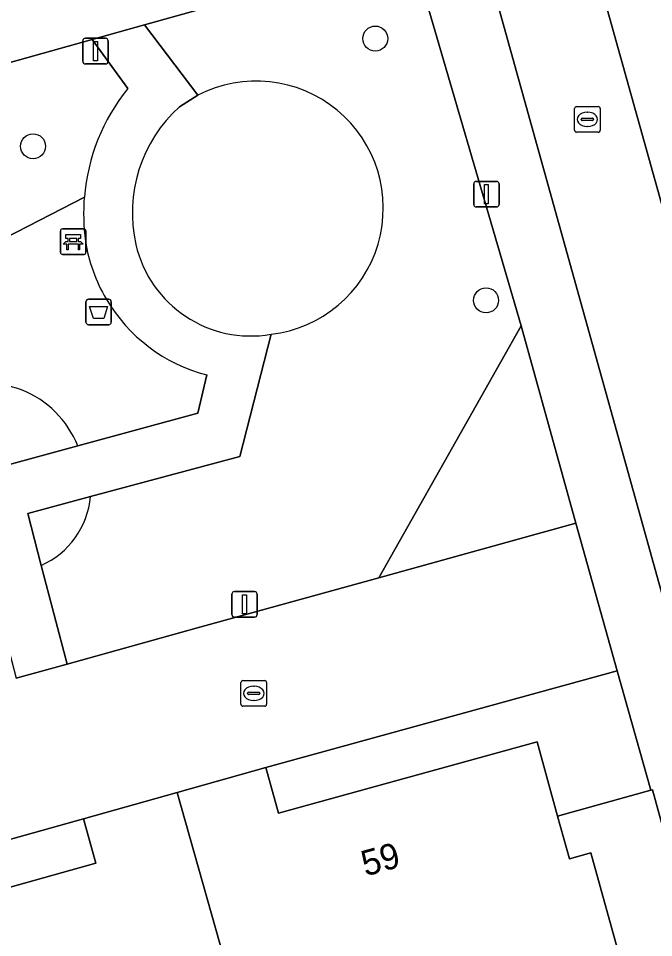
# Model space of a CAD drawing. Extents: x 159626 to 160723, y 388173 to 389416.
# Drawn here: x 159837.12 to 159861.97, y 388412.83 to 388448.77 of the extents above; entities that cross this region are included whole.
import ezdxf

# ---------------------------------------------------------------- set-up
doc = ezdxf.new("R2010")
doc.units = 0
for name, color, linetype in [('IMGEO_Afvalbak', 7, 'Continuous'), ('IMGEO_Bank', 7, 'Continuous'), ('IMGEO_Boom', 7, 'Continuous'), ('IMGEO_Erf', 7, 'Continuous'), ('IMGEO_Groenvoorziening', 7, 'Continuous'), ('IMGEO_Kolk', 7, 'Continuous'), ('IMGEO_Lichtmast', 7, 'Continuous'), ('IMGEO_Pand', 7, 'Continuous'), ('IMGEO_Pand_nummerreeks', 7, 'Continuous'), ('IMGEO_Rijbaan_lokaal_open', 7, 'Continuous'), ('IMGEO_Terreindeel_open', 7, 'Continuous'), ('IMGEO_Voetpad_open', 7, 'Continuous')]:
    doc.layers.add(name, color=color, linetype=linetype)

msp = doc.modelspace()

# ---------------------------------------------------------------- linework, layer by layer
at = {"layer": 'IMGEO_Afvalbak'}
for p, q in [((159839.768, 388436.896), (159839.768, 388437.696)), ((159839.768, 388437.696), (159839.768, 388436.896)), ((159839.868, 388437.796), (159840.658, 388437.796)), ((159840.658, 388437.796), (159839.868, 388437.796)), ((159840.758, 388437.696), (159840.758, 388436.896)), ((159840.758, 388436.896), (159840.758, 388437.696)), ((159840.658, 388436.796), (159839.868, 388436.796)), ((159839.868, 388436.796), (159840.658, 388436.796))]:
    msp.add_line(p, q, dxfattribs=at)
msp.add_lwpolyline([(159839.911, 388437.51), (159840.615, 388437.51), (159840.466, 388437.04), (159840.06, 388437.04), (159839.911, 388437.51)], dxfattribs=at)
for centre, start, end in [((159839.868, 388437.696), 90, 180), ((159839.868, 388437.696), 90, 180), ((159840.658, 388437.696), 0, 90), ((159840.658, 388437.696), 360, 90), ((159839.868, 388436.896), 180, 270), ((159839.868, 388436.896), 180, 270), ((159840.658, 388436.896), 270, 0), ((159840.658, 388436.896), 270, 0)]:
    msp.add_arc(centre, 0.1, start, end, dxfattribs=at)
at = {"layer": 'IMGEO_Bank'}
for p, q in [((159838.768, 388439.619), (159838.768, 388440.46)), ((159838.768, 388440.46), (159838.768, 388439.619)), ((159838.843, 388440.544), (159839.684, 388440.544)), ((159839.684, 388440.544), (159838.843, 388440.544)), ((159839.768, 388440.469), (159839.768, 388439.628)), ((159839.768, 388439.628), (159839.768, 388440.469)), ((159839.465, 388439.942), (159839.072, 388439.942)), ((159839.077, 388440.05), (159839.077, 388440.156)), ((159839.121, 388440.156), (159839.121, 388440.05)), ((159839.409, 388440.162), (159839.127, 388440.162)), ((159839.127, 388440.044), (159839.409, 388440.044)), ((159839.415, 388440.05), (159839.415, 388440.156)), ((159839.459, 388440.156), (159839.459, 388440.05)), ((159839.693, 388439.544), (159838.852, 388439.544)), ((159838.852, 388439.544), (159839.693, 388439.544))]:
    msp.add_line(p, q, dxfattribs=at)
for points in [[(159839.071, 388440.162), (159838.985, 388440.162), (159838.985, 388440.323), (159839.548, 388440.323), (159839.548, 388440.162), (159839.465, 388440.162)], [(159839.015, 388439.942), (159838.873, 388439.942), (159838.985, 388440.044), (159839.071, 388440.044)], [(159839.065, 388439.935), (159839.065, 388439.728), (159839.022, 388439.728), (159839.022, 388439.935)], [(159839.465, 388440.044), (159839.548, 388440.044), (159839.66, 388439.942), (159839.521, 388439.942)], [(159839.515, 388439.935), (159839.515, 388439.728), (159839.471, 388439.728), (159839.471, 388439.935)]]:
    msp.add_lwpolyline(points, dxfattribs=at)
for centre, radius, start, end in [((159838.846, 388440.466), 0.0779, 92.4484, 184.2845), ((159838.846, 388440.466), 0.0779, 92.4484, 184.2845), ((159839.69, 388440.466), 0.0779, 2.4484, 94.2845), ((159839.69, 388440.466), 0.0779, 2.4484, 94.2845), ((159839.015, 388439.935), 0.00671, 2.8957, 87.1043), ((159839.072, 388439.935), 0.00671, 92.8957, 177.1043), ((159839.07, 388440.155), 0.00671, 2.8957, 87.1043), ((159839.07, 388440.051), 0.00671, 272.8957, 357.1043), ((159839.127, 388440.155), 0.00671, 92.8957, 177.1043), ((159839.127, 388440.051), 0.00671, 182.8957, 267.1043), ((159839.409, 388440.155), 0.00671, 2.8957, 87.1043), ((159839.409, 388440.051), 0.00671, 272.8957, 357.1043), ((159839.466, 388440.155), 0.00671, 92.8957, 177.1043), ((159839.466, 388440.051), 0.00671, 182.8957, 267.1043), ((159839.464, 388439.935), 0.00671, 2.8957, 87.1043), ((159839.521, 388439.935), 0.00671, 92.8957, 177.1043), ((159838.846, 388439.622), 0.0779, 182.4484, 274.2845), ((159838.846, 388439.622), 0.0779, 182.4484, 274.2845), ((159839.69, 388439.622), 0.0779, 272.4484, 4.2845), ((159839.69, 388439.622), 0.0779, 272.4484, 4.2845)]:
    msp.add_arc(centre, radius, start, end, dxfattribs=at)
at = {"layer": 'IMGEO_Boom'}
for centre in [(159851.082, 388447.985), (159837.698, 388443.774), (159855.414, 388437.748)]:
    msp.add_circle(centre, 0.489, dxfattribs=at)
at = {"layer": 'IMGEO_Erf'}
msp.add_lwpolyline([(159860.545, 388423.261), (159846.806, 388419.48), (159847.3, 388417.69), (159857.414, 388420.486), (159858.215, 388417.585), (159861.857, 388418.591)], close=True, dxfattribs=at)
msp.add_lwpolyline([(159830.091, 388412.921), (159840.153, 388415.744), (159839.667, 388417.477), (159825.91, 388413.624)], dxfattribs=at)
at = {"layer": 'IMGEO_Groenvoorziening'}
for points in [[(159856.782, 388436.748), (159852.499, 388451.444), (159842.058, 388448.523), (159844.146, 388445.771)], [(159841.398, 388446.031), (159840.008, 388447.95), (159826.869, 388444.275), (159824.589, 388440.247), (159824.515, 388440.117), (159827.303, 388430.087), (159831.259, 388432.395), (159829.968, 388436.783), (159839.703, 388441.786)], [(159844.146, 388445.771), (159843.43, 388445.32)], [(159839.703, 388441.786), (159829.968, 388436.783), (159831.259, 388432.395), (159833.723, 388433.861)], [(159838.018, 388427.383), (159839.027, 388423.524), (159844.081, 388424.925), (159851.216, 388426.903), (159856.782, 388436.748)], [(159847.006, 388436.421), (159845.791, 388431.645), (159839.947, 388430.073)], [(159839.443, 388432.058), (159844.144, 388433.339), (159844.5, 388434.83)]]:
    msp.add_lwpolyline(points, dxfattribs=at)
msp.add_lwpolyline([(159856.782, 388436.748), (159851.216, 388426.903), (159858.925, 388429.04)], close=True, dxfattribs=at)
for centre, radius, start, end in [((159846.424, 388441.355), 4.969, 276.7287, 117.2872), ((159846.424, 388441.355), 4.969, 276.7287, 117.2872), ((159847.529, 388441.122), 7.854, 141.3168, 175.1502), ((159847.157, 388441.17), 5.578, 131.9241, 192.8713), ((159847.559, 388441.127), 7.884, 175.2053, 187.7272), ((159846.091, 388441.062), 6.422, 188.9115, 210.4635), ((159846.22, 388440.976), 4.622, 193.1132, 279.7872), ((159846.111, 388441.066), 6.441, 210.4092, 255.517), ((159835.854, 388430.645), 3.858, 21.4873, 116.3073), ((159836.669, 388430.387), 3.293, 294.1862, 354.5251)]:
    msp.add_arc(centre, radius, start, end, dxfattribs=at)
at = {"layer": 'IMGEO_Kolk'}
for p, q in [((159858.877, 388444.398), (159858.877, 388445.25)), ((159858.952, 388445.324), (159859.804, 388445.324)), ((159859.878, 388445.25), (159859.878, 388444.398)), ((159859.365, 388445.104), (159859.39, 388445.104)), ((159859.136, 388444.818), (159859.136, 388444.83)), ((159859.574, 388444.781), (159859.176, 388444.781)), ((159859.179, 388444.867), (159859.577, 388444.867)), ((159859.388, 388444.544), (159859.363, 388444.544)), ((159859.62, 388444.83), (159859.62, 388444.818)), ((159859.804, 388444.324), (159858.952, 388444.324)), ((159845.829, 388421.953), (159845.829, 388422.805)), ((159845.904, 388422.879), (159846.756, 388422.879)), ((159846.317, 388422.659), (159846.342, 388422.659)), ((159846.83, 388422.805), (159846.83, 388421.953)), ((159846.088, 388422.373), (159846.088, 388422.385)), ((159846.526, 388422.336), (159846.128, 388422.336)), ((159846.131, 388422.422), (159846.529, 388422.422)), ((159846.572, 388422.385), (159846.572, 388422.373)), ((159846.756, 388421.879), (159845.904, 388421.879)), ((159846.34, 388422.099), (159846.315, 388422.099))]:
    msp.add_line(p, q, dxfattribs=at)
for points in [[(159858.877, 388444.398), (159858.877, 388445.25)], [(159858.952, 388445.324), (159859.804, 388445.324)], [(159859.878, 388445.25), (159859.878, 388444.398)], [(159859.804, 388444.324), (159858.952, 388444.324)], [(159845.829, 388421.953), (159845.829, 388422.805)], [(159845.904, 388422.879), (159846.756, 388422.879)], [(159846.83, 388422.805), (159846.83, 388421.953)], [(159846.756, 388421.879), (159845.904, 388421.879)]]:
    msp.add_lwpolyline(points, dxfattribs=at)
for centre, radius, start, end in [((159858.954, 388445.248), 0.0765, 91.552, 178.448), ((159858.954, 388445.248), 0.0765, 91.552, 178.448), ((159859.802, 388445.248), 0.0765, 1.552, 88.448), ((159859.802, 388445.248), 0.0765, 1.552, 88.448), ((159859.176, 388444.827), 0.0403, 85.8775, 175.7526), ((159859.173, 388444.817), 0.0366, 178.938, 274.7102), ((159859.577, 388444.824), 0.043, 264.8664, 352.4533), ((159859.581, 388444.829), 0.0386, 1.7309, 96.639), ((159858.954, 388444.4), 0.0765, 181.552, 268.448), ((159858.954, 388444.4), 0.0765, 181.552, 268.448), ((159859.802, 388444.4), 0.0765, 271.552, 358.448), ((159859.802, 388444.4), 0.0765, 271.552, 358.448), ((159845.906, 388422.803), 0.0765, 91.552, 178.448), ((159845.906, 388422.803), 0.0765, 91.552, 178.448), ((159846.754, 388422.803), 0.0765, 1.552, 88.448), ((159846.754, 388422.803), 0.0765, 1.552, 88.448), ((159846.128, 388422.382), 0.0403, 85.8775, 175.7526), ((159846.125, 388422.372), 0.0366, 178.938, 274.7102), ((159846.529, 388422.379), 0.043, 264.8664, 352.4533), ((159846.533, 388422.384), 0.0386, 1.7309, 96.639), ((159845.906, 388421.955), 0.0765, 181.552, 268.448), ((159845.906, 388421.955), 0.0765, 181.552, 268.448), ((159846.754, 388421.955), 0.0765, 271.552, 358.448), ((159846.754, 388421.955), 0.0765, 271.552, 358.448)]:
    msp.add_arc(centre, radius, start, end, dxfattribs=at)
for centre, major_axis, ratio, start_param, end_param in [((159859.364, 388444.824), (-0.387, 0.002), 0.722429, 4.712389, 7.853982), ((159859.389, 388444.824), (-0.39, 0.002), 0.717154, 1.570796, 4.712389), ((159846.316, 388422.379), (-0.387, 0.002), 0.722429, 4.712389, 7.853982), ((159846.341, 388422.379), (-0.39, 0.002), 0.717154, 1.570796, 4.712389)]:
    msp.add_ellipse(centre, major_axis=major_axis, ratio=ratio, start_param=start_param, end_param=end_param, dxfattribs=at)
at = {"layer": 'IMGEO_Lichtmast'}
for p, q in [((159839.642, 388447.095), (159839.642, 388447.895)), ((159839.642, 388447.895), (159839.642, 388447.095)), ((159839.742, 388447.995), (159840.532, 388447.995)), ((159840.532, 388447.995), (159839.742, 388447.995)), ((159840.632, 388447.895), (159840.632, 388447.095)), ((159840.632, 388447.095), (159840.632, 388447.895)), ((159840.532, 388446.995), (159839.742, 388446.995)), ((159839.742, 388446.995), (159840.532, 388446.995)), ((159855.032, 388442.401), (159855.822, 388442.401)), ((159855.822, 388442.401), (159855.032, 388442.401)), ((159854.932, 388441.501), (159854.932, 388442.301)), ((159854.932, 388442.301), (159854.932, 388441.501)), ((159855.922, 388442.301), (159855.922, 388441.501)), ((159855.922, 388441.501), (159855.922, 388442.301)), ((159855.822, 388441.401), (159855.032, 388441.401)), ((159855.032, 388441.401), (159855.822, 388441.401)), ((159845.472, 388425.46), (159845.472, 388426.26)), ((159845.472, 388426.26), (159845.472, 388425.46)), ((159845.572, 388426.36), (159846.362, 388426.36)), ((159846.362, 388426.36), (159845.572, 388426.36)), ((159846.462, 388426.26), (159846.462, 388425.46)), ((159846.462, 388425.46), (159846.462, 388426.26)), ((159846.362, 388425.36), (159845.572, 388425.36)), ((159845.572, 388425.36), (159846.362, 388425.36))]:
    msp.add_line(p, q, dxfattribs=at)
for points in [[(159840.062, 388447.87), (159840.212, 388447.87), (159840.212, 388447.12), (159840.062, 388447.12), (159840.062, 388447.87)], [(159855.352, 388442.276), (159855.502, 388442.276), (159855.502, 388441.526), (159855.352, 388441.526), (159855.352, 388442.276)], [(159845.892, 388426.235), (159846.042, 388426.235), (159846.042, 388425.485), (159845.892, 388425.485), (159845.892, 388426.235)]]:
    msp.add_lwpolyline(points, dxfattribs=at)
for centre, start, end in [((159839.742, 388447.895), 90, 180), ((159839.742, 388447.895), 90, 180), ((159840.532, 388447.895), 0, 90), ((159840.532, 388447.895), 360, 90), ((159839.742, 388447.095), 180, 270), ((159839.742, 388447.095), 180, 270), ((159840.532, 388447.095), 270, 0), ((159840.532, 388447.095), 270, 0), ((159855.032, 388442.301), 90, 180), ((159855.032, 388442.301), 90, 180), ((159855.822, 388442.301), 0, 90), ((159855.822, 388442.301), 360, 90), ((159855.032, 388441.501), 180, 270), ((159855.032, 388441.501), 180, 270), ((159855.822, 388441.501), 270, 0), ((159855.822, 388441.501), 270, 0), ((159845.572, 388426.26), 90, 180), ((159845.572, 388426.26), 90, 180), ((159846.362, 388426.26), 0, 90), ((159846.362, 388426.26), 360, 90), ((159845.572, 388425.46), 180, 270), ((159845.572, 388425.46), 180, 270), ((159846.362, 388425.46), 270, 0), ((159846.362, 388425.46), 270, 0)]:
    msp.add_arc(centre, 0.1, start, end, dxfattribs=at)
at = {"layer": 'IMGEO_Pand'}
for points in [[(159855.003, 388411.473), (159855.281, 388410.472), (159860.47, 388411.907), (159860.669, 388411.962), (159859.514, 388416.145), (159858.677, 388415.914), (159858.215, 388417.585), (159857.414, 388420.486), (159847.3, 388417.69), (159846.806, 388419.48), (159843.335, 388418.506), (159848.169, 388401.396), (159848.191, 388401.319), (159848.709, 388401.462), (159853.528, 388402.794), (159851.404, 388410.478)], [(159843.335, 388418.506), (159839.667, 388417.477), (159840.153, 388415.744), (159830.091, 388412.921), (159831.334, 388408.492), (159830.419, 388408.236), (159831.526, 388404.288), (159836.918, 388405.801), (159836.707, 388406.547), (159840.393, 388407.588), (159842.588, 388399.819), (159848.169, 388401.396)], [(159861.857, 388418.591), (159858.215, 388417.585), (159858.677, 388415.914), (159859.514, 388416.145), (159860.669, 388411.962), (159860.47, 388411.907), (159860.815, 388410.657), (159863.885, 388411.505), (159861.923, 388418.609)]]:
    msp.add_lwpolyline(points, close=True, dxfattribs=at)
at = {"layer": 'IMGEO_Rijbaan_lokaal_open'}
msp.add_lwpolyline([(159871.183, 388409.697), (159858.976, 388453.345), (159890.351, 388462.109), (159889.278, 388465.962), (159854.007, 388456.02), (159867.243, 388408.503)], close=True, dxfattribs=at)
for points in [[(159826.869, 388444.275), (159840.008, 388447.95), (159842.058, 388448.523), (159852.499, 388451.444), (159850.882, 388457.196), (159845.063, 388455.568), (159841.477, 388454.552), (159838.132, 388453.605), (159819.193, 388448.425)], [(159825.91, 388413.624), (159839.667, 388417.477), (159843.335, 388418.506), (159846.806, 388419.48), (159860.545, 388423.261), (159858.925, 388429.04), (159851.216, 388426.903), (159844.081, 388424.925), (159839.027, 388423.524), (159837.038, 388422.972)]]:
    msp.add_lwpolyline(points, dxfattribs=at)
at = {"layer": 'IMGEO_Terreindeel_open'}
for points in [[(159836.062, 388426.725), (159834.992, 388430.845), (159839.443, 388432.058)], [(159839.947, 388430.073), (159837.488, 388429.411), (159838.018, 388427.383)]]:
    msp.add_lwpolyline(points, dxfattribs=at)
for centre, radius, start, end in [((159835.854, 388430.645), 3.858, 21.4873, 116.3073), ((159836.669, 388430.387), 3.293, 294.1862, 354.5251)]:
    msp.add_arc(centre, radius, start, end, dxfattribs=at)
at = {"layer": 'IMGEO_Voetpad_open'}
for points in [[(159890.763, 388466.088), (159889.278, 388465.962), (159890.351, 388462.109), (159858.976, 388453.345), (159871.183, 388409.697), (159871.974, 388406.867), (159883.064, 388367.211), (159868.371, 388363.142), (159877.583, 388329.947), (159898.714, 388335.876), (159901.439, 388336.64), (159939.056, 388347.194), (159938.495, 388349.196), (159935.001, 388348.184)], [(159877.981, 388369.955), (159868.033, 388405.666), (159867.243, 388408.503), (159854.007, 388456.02), (159889.278, 388465.962)], [(159877.039, 388464.539), (159873.439, 388463.52), (159870.121, 388462.581), (159850.882, 388457.196), (159852.499, 388451.444), (159856.782, 388436.748), (159858.925, 388429.04), (159860.545, 388423.261), (159861.857, 388418.591), (159861.923, 388418.609), (159863.885, 388411.505), (159866.166, 388403.253), (159869.862, 388390.097), (159870.943, 388386.198), (159871.789, 388383.149), (159874.651, 388372.898)], [(159843.43, 388445.32), (159844.146, 388445.771), (159842.058, 388448.523), (159840.008, 388447.95), (159841.398, 388446.031)], [(159844.5, 388434.83), (159844.144, 388433.339), (159839.443, 388432.058), (159834.992, 388430.845), (159836.062, 388426.725), (159836.424, 388425.331), (159837.038, 388422.972), (159839.027, 388423.524), (159838.018, 388427.383), (159837.488, 388429.411), (159839.947, 388430.073), (159845.791, 388431.645), (159847.006, 388436.421)]]:
    msp.add_lwpolyline(points, dxfattribs=at)
for centre, radius, start, end in [((159847.529, 388441.122), 7.854, 141.3168, 175.1502), ((159847.157, 388441.17), 5.578, 131.9241, 192.8713), ((159847.559, 388441.127), 7.884, 175.2053, 187.7272), ((159846.091, 388441.062), 6.422, 188.9115, 210.4635), ((159846.22, 388440.976), 4.622, 193.1132, 279.7872), ((159846.111, 388441.066), 6.441, 210.4092, 255.517)]:
    msp.add_arc(centre, radius, start, end, dxfattribs=at)

# ---------------------------------------------------------------- texts
at = {"layer": 'IMGEO_Pand_nummerreeks'}
msp.add_text('59', height=1, rotation=15.5042, dxfattribs=at).set_placement((159850.697, 388415.217))

doc.saveas('drawing.dxf')
